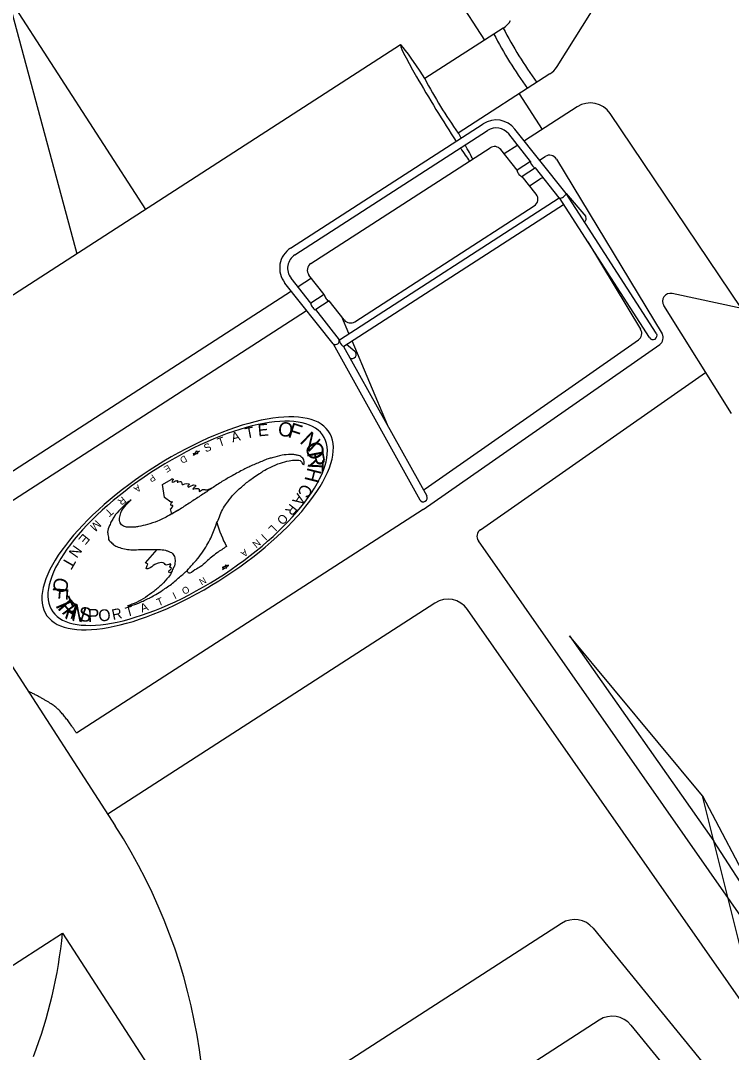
# Model space of a CAD drawing. Extents: x 2160312 to 2162215, y 789569 to 792090.
# Drawn here: x 2160629.46 to 2160646.64, y 791265.83 to 791290.78 of the extents above; entities that cross this region are included whole.
import ezdxf

# ---------------------------------------------------------------- set-up
doc = ezdxf.new("R2010")
doc.units = 0
doc.layers.add('DEV TITLE SHEET CELL', color=7, linetype='Continuous')

msp = doc.modelspace()

# ---------------------------------------------------------------- linework, layer by layer
at = {"layer": 'DEV TITLE SHEET CELL'}
for p, q in [((2160627.197, 791294.398), (2160632.481, 791286.212)), ((2160642.426, 791289.665), (2160645.071, 791293.874)), ((2160639.606, 791291.955), (2160640.671, 791290.305)), ((2160629.138, 791291.39), (2160630.822, 791285.141)), ((2160641.125, 791290.598), (2160639.229, 791289.374)), ((2160638.641, 791290.189), (2160626.105, 791282.097)), ((2160642.249, 791289.487), (2160640.038, 791288.059)), ((2160641.508, 791289.008), (2160642.066, 791288.145)), ((2160642.913, 791288.692), (2160641.637, 791287.868)), ((2160646.884, 791283.816), (2160643.707, 791288.529)), ((2160635.986, 791285.278), (2160640.641, 791288.283)), ((2160642.643, 791286.6), (2160641.408, 791288.156)), ((2160636.091, 791285.116), (2160640.745, 791288.121)), ((2160641.785, 791287.37), (2160641.257, 791288.036)), ((2160636.478, 791284.907), (2160640.807, 791287.702)), ((2160641.459, 791287.16), (2160641.063, 791287.659)), ((2160641.474, 791287.763), (2160641.148, 791287.553)), ((2160642.004, 791287.405), (2160642.142, 791287.493)), ((2160642.412, 791287.431), (2160644.963, 791283.203)), ((2160641.783, 791287.369), (2160641.459, 791287.16)), ((2160641.903, 791287.216), (2160641.58, 791287.008)), ((2160642.48, 791286.495), (2160641.905, 791287.219)), ((2160641.921, 791286.578), (2160641.58, 791287.008)), ((2160641.757, 791286.785), (2160642.017, 791286.953)), ((2160637.164, 791283.063), (2160642.48, 791286.495)), ((2160644.662, 791283.116), (2160642.481, 791286.495)), ((2160644.824, 791283.221), (2160642.643, 791286.6)), ((2160642.643, 791286.6), (2160643.119, 791286.037)), ((2160637.271, 791282.902), (2160642.585, 791286.333)), ((2160637.538, 791283.497), (2160641.875, 791286.296)), ((2160643.171, 791285.426), (2160644.446, 791283.313)), ((2160637.011, 791282.964), (2160635.847, 791284.432)), ((2160636.475, 791283.943), (2160635.998, 791284.552)), ((2160636.492, 791284.547), (2160636.166, 791284.337)), ((2160636.801, 791284.153), (2160636.43, 791284.625)), ((2160636.005, 791284.233), (2160626.216, 791277.914)), ((2160646.889, 791283.82), (2160645.208, 791284.177)), ((2160636.801, 791284.153), (2160636.475, 791283.943)), ((2160636.92, 791284), (2160636.595, 791283.79)), ((2160637.281, 791283.54), (2160636.92, 791284)), ((2160627.632, 791278.127), (2160636.373, 791283.769)), ((2160637.164, 791283.063), (2160636.595, 791283.79)), ((2160646.638, 791281.28), (2160645.005, 791283.886)), ((2160637.394, 791283.211), (2160637.224, 791283.613)), ((2160637.011, 791282.964), (2160639.108, 791279.192)), ((2160637.538, 791282.779), (2160637.336, 791282.946)), ((2160638.327, 791281.004), (2160637.47, 791283.031)), ((2160639.193, 791278.956), (2160644.908, 791282.946)), ((2160639.235, 791279.456), (2160644.391, 791283.055)), ((2160637.267, 791282.901), (2160639.276, 791279.286)), ((2160640.573, 791278.469), (2160646.017, 791282.27)), ((2160633.627, 791280.304), (2160633.688, 791280.329)), ((2160633.627, 791280.304), (2160633.688, 791280.329)), ((2160633.669, 791280.304), (2160633.627, 791280.304)), ((2160633.669, 791280.304), (2160633.627, 791280.304)), ((2160633.638, 791280.26), (2160633.669, 791280.304)), ((2160633.638, 791280.26), (2160633.669, 791280.304)), ((2160633.694, 791280.302), (2160633.638, 791280.26)), ((2160633.694, 791280.302), (2160633.638, 791280.26)), ((2160633.688, 791280.329), (2160633.718, 791280.373)), ((2160633.688, 791280.329), (2160633.718, 791280.373)), ((2160633.736, 791280.3), (2160633.694, 791280.302)), ((2160633.736, 791280.3), (2160633.694, 791280.302)), ((2160633.718, 791280.373), (2160633.725, 791280.345)), ((2160633.718, 791280.373), (2160633.725, 791280.345)), ((2160633.725, 791280.345), (2160633.783, 791280.369)), ((2160633.725, 791280.345), (2160633.783, 791280.369)), ((2160633.783, 791280.369), (2160633.73, 791280.327)), ((2160633.783, 791280.369), (2160633.73, 791280.327)), ((2160633.73, 791280.327), (2160633.736, 791280.3)), ((2160633.73, 791280.327), (2160633.736, 791280.3)), ((2160636.313, 791280.047), (2160636.305, 791280.046)), ((2160636.313, 791280.047), (2160636.305, 791280.046)), ((2160636.313, 791280.047), (2160636.305, 791280.046)), ((2160632.888, 791279.564), (2160633.1, 791279.682)), ((2160632.888, 791279.564), (2160633.1, 791279.682)), ((2160632.939, 791279.245), (2160632.888, 791279.564)), ((2160632.939, 791279.245), (2160632.888, 791279.564)), ((2160633.094, 791279.135), (2160632.939, 791279.245)), ((2160633.094, 791279.135), (2160632.939, 791279.245)), ((2160639.193, 791278.956), (2160630.814, 791273.547)), ((2160633.112, 791278.847), (2160633.084, 791278.976)), ((2160633.112, 791278.847), (2160633.084, 791278.976)), ((2160634.205, 791278.639), (2160634.205, 791278.639)), ((2160634.205, 791278.639), (2160634.205, 791278.639)), ((2160648.429, 791266.88), (2160640.525, 791278.2)), ((2160632.475, 791277.671), (2160632.76, 791277.988)), ((2160632.475, 791277.671), (2160632.76, 791277.988)), ((2160632.76, 791277.988), (2160632.76, 791277.988)), ((2160632.76, 791277.988), (2160632.76, 791277.988)), ((2160634.393, 791277.576), (2160634.333, 791277.551)), ((2160634.393, 791277.576), (2160634.333, 791277.551)), ((2160634.333, 791277.551), (2160634.373, 791277.55)), ((2160634.333, 791277.551), (2160634.373, 791277.55)), ((2160634.373, 791277.55), (2160634.343, 791277.507)), ((2160634.373, 791277.55), (2160634.343, 791277.507)), ((2160634.343, 791277.507), (2160634.399, 791277.549)), ((2160634.343, 791277.507), (2160634.399, 791277.549)), ((2160634.422, 791277.619), (2160634.393, 791277.576)), ((2160634.422, 791277.619), (2160634.393, 791277.576)), ((2160634.399, 791277.549), (2160634.442, 791277.548)), ((2160634.399, 791277.549), (2160634.442, 791277.548)), ((2160634.429, 791277.592), (2160634.422, 791277.619)), ((2160634.429, 791277.592), (2160634.422, 791277.619)), ((2160634.487, 791277.615), (2160634.429, 791277.592)), ((2160634.487, 791277.615), (2160634.429, 791277.592)), ((2160634.434, 791277.574), (2160634.487, 791277.615)), ((2160634.434, 791277.574), (2160634.487, 791277.615)), ((2160634.442, 791277.548), (2160634.434, 791277.574)), ((2160634.442, 791277.548), (2160634.434, 791277.574)), ((2160633.895, 791277.019), (2160633.895, 791277.019)), ((2160633.895, 791277.019), (2160633.895, 791277.019)), ((2160639.475, 791276.695), (2160631.565, 791271.589)), ((2160648.626, 791264.563), (2160640.264, 791276.54)), ((2160645.942, 791272.037), (2160642.724, 791275.906)), ((2160642.724, 791275.906), (2160646.217, 791270.935)), ((2160629.174, 791275.293), (2160631.748, 791271.306)), ((2160645.942, 791272.037), (2160647.839, 791268.415)), ((2160646.854, 791268.391), (2160645.942, 791272.037)), ((2160647.839, 791268.415), (2160646.217, 791270.935)), ((2160642.535, 791268.951), (2160633.917, 791263.388)), ((2160626.634, 791266.238), (2160630.476, 791268.718)), ((2160630.476, 791268.718), (2160633.917, 791263.388)), ((2160643.297, 791268.831), (2160650.056, 791260.549)), ((2160643.446, 791266.614), (2160633.389, 791260.122))]:
    msp.add_line(p, q, dxfattribs=at)
msp.add_lwpolyline([(2160644.208, 791266.493), (2160650.828, 791258.381), (2160655.726, 791248.545)], dxfattribs=at)
for centre, radius, start, end in [((2160640.811, 791291.084), 0.579, 302.8433, 327.8433), ((2160650.001, 791295.144), 10.24, 207.2706, 215.9184), ((2160650.226, 791295.29), 10.24, 207.2706, 215.9184), ((2160641.936, 791289.973), 0.579, 302.8433, 327.8433), ((2160648.33, 791294.066), 10.24, 207.2706, 215.9184), ((2160643.227, 791288.206), 0.579, 33.9826, 122.8433), ((2160640.954, 791287.796), 0.579, 38.4237, 122.8433), ((2160640.954, 791287.796), 0.386, 38.4237, 122.8433), ((2160640.912, 791287.539), 0.193, 38.4237, 122.8433), ((2160642.246, 791287.331), 0.193, 31.1078, 122.8433), ((2160642.122, 791286.791), 0.193, 98.4709, 122.8433), ((2160641.77, 791286.458), 0.193, 302.8433, 38.4237), ((2160643.035, 791285.989), 0.0965, 304.5431, 29.5006), ((2160636.3, 791284.792), 0.579, 122.8433, 218.4237), ((2160636.3, 791284.792), 0.386, 122.8433, 218.4237), ((2160636.582, 791284.744), 0.193, 122.8433, 218.0835), ((2160645.168, 791283.988), 0.193, 78.0134, 212.0784), ((2160637.433, 791283.659), 0.193, 218.0835, 302.8433), ((2160644.28, 791283.214), 0.193, 304.9228, 31.1078), ((2160644.746, 791283.163), 0.0965, 209.0651, 29.0651), ((2160644.797, 791283.104), 0.193, 304.9228, 31.1078), ((2160637.07, 791283.036), 0.0926, 209.4294, 50.8189), ((2160637.476, 791282.705), 0.0965, 234.6212, 50.4547), ((2160639.125, 791279.614), 0.193, 291.5281, 304.9228), ((2160639.192, 791279.239), 0.0965, 209.0651, 29.0651), ((2160640.683, 791278.311), 0.193, 124.9228, 214.9228), ((2160639.789, 791276.209), 0.579, 34.9228, 122.8433), ((2160620.295, 791263.912), 13.632, 343.8569, 32.8433), ((2160642.849, 791268.465), 0.579, 39.2178, 122.8433), ((2160618.976, 791269.857), 11.556, 339.0716, 354.3432), ((2160643.76, 791266.127), 0.579, 39.2178, 122.8433)]:
    msp.add_arc(centre, radius, start, end, dxfattribs=at)
for centre, major_axis, ratio, start_param, end_param in [((2160639.582, 791288.656), (-0.941, 1.533), 0.046583, 5.1713, 8.375165), ((2160639.582, 791288.656), (-0.941, 1.533), 0.046583, 4.195477, 4.283977), ((2160639.582, 791288.656), (-0.941, 1.533), 0.046583, 2.213476, 2.527889), ((2160639.582, 791288.656), (-0.941, 1.533), 0.046583, 3.752909, 4.070851), ((2160641.518, 791287.083), (0.0575, -0.0789), 0.259529, 3.225171, 6.472122), ((2160641.842, 791287.291), (0.0575, -0.0789), 0.259529, 3.225171, 6.472122), ((2160642.562, 791286.546), (0.081, 0.0538), 0.351139, 3.062724, 6.283185), ((2160636.535, 791283.865), (0.0575, -0.0789), 0.259529, 3.225171, 6.472122), ((2160636.86, 791284.075), (0.0575, -0.0789), 0.259529, 3.225171, 6.472122), ((2160637.217, 791282.983), (-0.0523, 0.0792), 0.293196, 6.282737, 9.424275), ((2160633.497, 791278.623), (3.418, 2.207), 0.387649, 4.580113, 7.721705), ((2160633.497, 791278.623), (3.418, 2.207), 0.387649, 4.580113, 7.721705), ((2160633.497, 791278.623), (3.276, 2.115), 0.387649, 4.580113, 7.721705), ((2160633.497, 791278.623), (3.276, 2.115), 0.387649, 4.580113, 7.721705), ((2160633.497, 791278.623), (-3.418, -2.207), 0.387649, 4.580113, 7.721705), ((2160633.497, 791278.623), (-3.418, -2.207), 0.387649, 4.580113, 7.721705), ((2160633.497, 791278.623), (-3.276, -2.115), 0.387649, 4.580113, 7.721705), ((2160633.497, 791278.623), (-3.276, -2.115), 0.387649, 4.580113, 7.721705), ((2160652.622, 791289.414), (-18.024, -11.635), 0.387649, 6.075485, 6.077223), ((2160652.622, 791289.414), (-18.024, -11.635), 0.387649, 6.075485, 6.077223), ((2160652.622, 791289.414), (-18.024, -11.635), 0.387649, 6.170414, 6.243823), ((2160652.622, 791289.414), (-18.024, -11.635), 0.387649, 6.170414, 6.243823)]:
    msp.add_ellipse(centre, major_axis=major_axis, ratio=ratio, start_param=start_param, end_param=end_param, dxfattribs=at)
for points in [[(2160636.305, 791280.046), (2160636.317, 791280.094), (2160636.281, 791280.195), (2160636.179, 791280.26), (2160636.165, 791280.263), (2160636.089, 791280.281), (2160635.982, 791280.285), (2160635.781, 791280.269), (2160635.543, 791280.208), (2160635.442, 791280.181), (2160635.321, 791280.133), (2160635.065, 791280.027), (2160634.822, 791279.908), (2160634.541, 791279.755), (2160634.297, 791279.612), (2160634.051, 791279.45), (2160633.804, 791279.285), (2160633.563, 791279.128), (2160633.315, 791278.967), (2160633.065, 791278.823), (2160633.043, 791278.811), (2160632.771, 791278.678), (2160632.525, 791278.593), (2160632.313, 791278.544), (2160632.214, 791278.53), (2160632.109, 791278.531), (2160632.049, 791278.531), (2160631.95, 791278.557), (2160631.866, 791278.635), (2160631.853, 791278.75), (2160631.883, 791278.876), (2160631.979, 791279.027), (2160632.131, 791279.19)], [(2160636.305, 791280.046), (2160636.317, 791280.094), (2160636.281, 791280.195), (2160636.179, 791280.26), (2160636.165, 791280.263), (2160636.089, 791280.281), (2160635.982, 791280.285), (2160635.781, 791280.269), (2160635.543, 791280.208), (2160635.442, 791280.181), (2160635.321, 791280.133), (2160635.065, 791280.027), (2160634.822, 791279.908), (2160634.541, 791279.755), (2160634.297, 791279.612), (2160634.051, 791279.45), (2160633.804, 791279.285), (2160633.563, 791279.128), (2160633.315, 791278.967), (2160633.065, 791278.823), (2160633.043, 791278.811), (2160632.771, 791278.678), (2160632.525, 791278.593), (2160632.313, 791278.544), (2160632.214, 791278.53), (2160632.109, 791278.531), (2160632.049, 791278.531), (2160631.95, 791278.557), (2160631.866, 791278.635), (2160631.853, 791278.75), (2160631.883, 791278.876), (2160631.979, 791279.027), (2160632.131, 791279.19)], [(2160632.044, 791276.626), (2160632.106, 791276.633), (2160632.325, 791276.702), (2160632.574, 791276.817), (2160632.598, 791276.829), (2160632.732, 791276.905), (2160632.887, 791277.003), (2160633.134, 791277.176), (2160633.355, 791277.367), (2160633.448, 791277.447), (2160633.535, 791277.539), (2160633.705, 791277.728), (2160633.839, 791277.902), (2160633.964, 791278.097), (2160634.057, 791278.263), (2160634.123, 791278.425), (2160634.183, 791278.585), (2160634.248, 791278.741), (2160634.318, 791278.907), (2160634.417, 791279.077), (2160634.429, 791279.092), (2160634.577, 791279.289), (2160634.771, 791279.477), (2160634.976, 791279.648), (2160635.088, 791279.73), (2160635.234, 791279.825), (2160635.317, 791279.881), (2160635.495, 791279.976), (2160635.741, 791280.081), (2160635.949, 791280.134), (2160636.119, 791280.153), (2160636.24, 791280.121), (2160636.305, 791280.046), (2160636.313, 791280.047)], [(2160632.044, 791276.626), (2160632.106, 791276.633), (2160632.325, 791276.702), (2160632.574, 791276.817), (2160632.598, 791276.829), (2160632.732, 791276.905), (2160632.887, 791277.003), (2160633.134, 791277.176), (2160633.355, 791277.367), (2160633.448, 791277.447), (2160633.535, 791277.539), (2160633.705, 791277.728), (2160633.839, 791277.902), (2160633.964, 791278.097), (2160634.057, 791278.263), (2160634.123, 791278.425), (2160634.183, 791278.585), (2160634.248, 791278.741), (2160634.318, 791278.907), (2160634.417, 791279.077), (2160634.429, 791279.092), (2160634.577, 791279.289), (2160634.771, 791279.477), (2160634.976, 791279.648), (2160635.088, 791279.73), (2160635.234, 791279.825), (2160635.317, 791279.881), (2160635.495, 791279.976), (2160635.741, 791280.081), (2160635.949, 791280.134), (2160636.119, 791280.153), (2160636.24, 791280.121), (2160636.305, 791280.046), (2160636.313, 791280.047)], [(2160633.1, 791279.682), (2160633.119, 791279.697), (2160633.146, 791279.693), (2160633.116, 791279.625), (2160633.164, 791279.627), (2160633.207, 791279.652), (2160633.254, 791279.658), (2160633.248, 791279.62), (2160633.333, 791279.636), (2160633.353, 791279.619), (2160633.366, 791279.564), (2160633.523, 791279.581), (2160633.538, 791279.559), (2160633.502, 791279.531), (2160633.499, 791279.51), (2160633.622, 791279.549), (2160633.641, 791279.552), (2160633.697, 791279.526), (2160633.679, 791279.501), (2160633.628, 791279.467), (2160633.62, 791279.454), (2160633.65, 791279.453), (2160633.718, 791279.466), (2160633.774, 791279.451), (2160633.774, 791279.397), (2160633.86, 791279.437), (2160633.954, 791279.429), (2160634.006, 791279.445), (2160634.056, 791279.471)], [(2160633.1, 791279.682), (2160633.119, 791279.697), (2160633.146, 791279.693), (2160633.116, 791279.625), (2160633.164, 791279.627), (2160633.207, 791279.652), (2160633.254, 791279.658), (2160633.248, 791279.62), (2160633.333, 791279.636), (2160633.353, 791279.619), (2160633.366, 791279.564), (2160633.523, 791279.581), (2160633.538, 791279.559), (2160633.502, 791279.531), (2160633.499, 791279.51), (2160633.622, 791279.549), (2160633.641, 791279.552), (2160633.697, 791279.526), (2160633.679, 791279.501), (2160633.628, 791279.467), (2160633.62, 791279.454), (2160633.65, 791279.453), (2160633.718, 791279.466), (2160633.774, 791279.451), (2160633.774, 791279.397), (2160633.86, 791279.437), (2160633.954, 791279.429), (2160634.006, 791279.445), (2160634.056, 791279.471)], [(2160634.057, 791279.454), (2160634.051, 791279.45), (2160633.804, 791279.285), (2160633.563, 791279.128), (2160633.315, 791278.967), (2160633.112, 791278.848)], [(2160634.057, 791279.454), (2160634.051, 791279.45), (2160633.804, 791279.285), (2160633.563, 791279.128), (2160633.315, 791278.967), (2160633.112, 791278.848)], [(2160632.131, 791279.19), (2160632.055, 791279.133), (2160631.872, 791278.963), (2160631.724, 791278.783), (2160631.716, 791278.768), (2160631.656, 791278.672), (2160631.612, 791278.572), (2160631.563, 791278.413), (2160631.581, 791278.286), (2160631.588, 791278.232), (2160631.625, 791278.187), (2160631.709, 791278.106), (2160631.817, 791278.049), (2160631.973, 791278.007), (2160632.122, 791277.985), (2160632.306, 791277.986), (2160632.493, 791277.991), (2160632.668, 791277.989), (2160632.845, 791277.986), (2160632.997, 791277.96), (2160633.009, 791277.955), (2160633.133, 791277.894), (2160633.185, 791277.791), (2160633.191, 791277.67), (2160633.179, 791277.599), (2160633.135, 791277.504), (2160633.117, 791277.449), (2160633.035, 791277.325), (2160632.874, 791277.145), (2160632.678, 791276.978), (2160632.476, 791276.831), (2160632.258, 791276.711), (2160632.044, 791276.626)], [(2160632.131, 791279.19), (2160632.055, 791279.133), (2160631.872, 791278.963), (2160631.724, 791278.783), (2160631.716, 791278.768), (2160631.656, 791278.672), (2160631.612, 791278.572), (2160631.563, 791278.413), (2160631.581, 791278.286), (2160631.588, 791278.232), (2160631.625, 791278.187), (2160631.709, 791278.106), (2160631.817, 791278.049), (2160631.973, 791278.007), (2160632.122, 791277.985), (2160632.306, 791277.986), (2160632.493, 791277.991), (2160632.668, 791277.989), (2160632.845, 791277.986), (2160632.997, 791277.96), (2160633.009, 791277.955), (2160633.133, 791277.894), (2160633.185, 791277.791), (2160633.191, 791277.67), (2160633.179, 791277.599), (2160633.135, 791277.504), (2160633.117, 791277.449), (2160633.035, 791277.325), (2160632.874, 791277.145), (2160632.678, 791276.978), (2160632.476, 791276.831), (2160632.258, 791276.711), (2160632.044, 791276.626)], [(2160633.084, 791278.976), (2160633.131, 791279.018), (2160633.141, 791279.051), (2160633.094, 791279.063), (2160633.091, 791279.09), (2160633.128, 791279.142), (2160633.094, 791279.135)], [(2160633.084, 791278.976), (2160633.131, 791279.018), (2160633.141, 791279.051), (2160633.094, 791279.063), (2160633.091, 791279.09), (2160633.128, 791279.142), (2160633.094, 791279.135)], [(2160633.482, 791277.48), (2160633.535, 791277.539), (2160633.705, 791277.728), (2160633.839, 791277.902), (2160633.964, 791278.097), (2160634.057, 791278.263), (2160634.123, 791278.425), (2160634.183, 791278.585), (2160634.205, 791278.639)], [(2160633.482, 791277.48), (2160633.535, 791277.539), (2160633.705, 791277.728), (2160633.839, 791277.902), (2160633.964, 791278.097), (2160634.057, 791278.263), (2160634.123, 791278.425), (2160634.183, 791278.585), (2160634.205, 791278.639)], [(2160632.76, 791277.988), (2160632.845, 791277.986), (2160632.997, 791277.96), (2160633.009, 791277.955), (2160633.133, 791277.894), (2160633.185, 791277.791), (2160633.191, 791277.67), (2160633.179, 791277.599), (2160633.135, 791277.504), (2160633.117, 791277.452)], [(2160632.76, 791277.988), (2160632.845, 791277.986), (2160632.997, 791277.96), (2160633.009, 791277.955), (2160633.133, 791277.894), (2160633.185, 791277.791), (2160633.191, 791277.67), (2160633.179, 791277.599), (2160633.135, 791277.504), (2160633.117, 791277.452)], [(2160634.435, 791278.063), (2160634.207, 791277.906), (2160633.946, 791277.692), (2160633.804, 791277.569), (2160633.674, 791277.496), (2160633.516, 791277.42), (2160633.484, 791277.48)], [(2160634.435, 791278.063), (2160634.207, 791277.906), (2160633.946, 791277.692), (2160633.804, 791277.569), (2160633.674, 791277.496), (2160633.516, 791277.42), (2160633.484, 791277.48)], [(2160633.116, 791277.452), (2160633.051, 791277.432), (2160633.041, 791277.454), (2160633.104, 791277.538), (2160633.068, 791277.577), (2160633.092, 791277.618), (2160633.09, 791277.634), (2160632.978, 791277.613), (2160632.94, 791277.65), (2160632.786, 791277.656), (2160632.703, 791277.629), (2160632.537, 791277.526), (2160632.499, 791277.527), (2160632.501, 791277.557), (2160632.532, 791277.633), (2160632.475, 791277.671)], [(2160633.116, 791277.452), (2160633.051, 791277.432), (2160633.041, 791277.454), (2160633.104, 791277.538), (2160633.068, 791277.577), (2160633.092, 791277.618), (2160633.09, 791277.634), (2160632.978, 791277.613), (2160632.94, 791277.65), (2160632.786, 791277.656), (2160632.703, 791277.629), (2160632.537, 791277.526), (2160632.499, 791277.527), (2160632.501, 791277.557), (2160632.532, 791277.633), (2160632.475, 791277.671)]]:
    msp.add_spline(points, degree=3, dxfattribs=at)
msp.add_open_spline([(2160630.814, 791273.547), (2160630.555, 791273.949), (2160630.167, 791274.313), (2160629.664, 791274.553)], degree=2, dxfattribs=at)
msp.add_open_spline([(2160630.814, 791273.547), (2160630.555, 791273.949), (2160630.167, 791274.313), (2160629.664, 791274.553)], degree=2, dxfattribs=at)

# ---------------------------------------------------------------- texts
for s, height, rotation, p in [('T', 0.26, 10.7589, (2160634.915, 791280.669)), ('E', 0.291, 5.2613, (2160635.205, 791280.723)), ('O', 0.345, 352.6392, (2160635.666, 791280.745)), ('F', 0.373, 341.953, (2160635.897, 791280.713)), ('T', 0.21, 19.1255, (2160634.261, 791280.469)), ('A', 0.234, 15.2685, (2160634.586, 791280.579)), ('N', 0.402, 316.5595, (2160636.188, 791280.586)), ('S', 0.191, 22.2189, (2160633.934, 791280.336)), ('O', 0.406, 297.4571, (2160636.301, 791280.476)), ('D', 0.162, 209.0421, (2160633.428, 791280.273)), ('R', 0.397, 281.2949, (2160636.378, 791280.328)), ('E', 0.157, 211.5092, (2160633.026, 791280.048)), ('H', 0.353, 256.0342, (2160636.399, 791279.988)), ('T', 0.38, 267.5346, (2160636.409, 791280.171)), ('P', 0.158, 214.4328, (2160632.652, 791279.815)), ('A', 0.163, 217.0274, (2160632.295, 791279.57)), ('C', 0.299, 242.0124, (2160636.274, 791279.601)), ('R', 0.173, 219.9192, (2160631.919, 791279.284)), ('A', 0.267, 235.9351, (2160636.148, 791279.367)), ('T', 0.187, 222.8194, (2160631.592, 791279.008)), ('R', 0.241, 231.6865, (2160635.978, 791279.115)), ('M', 0.207, 226.2777, (2160631.283, 791278.718)), ('O', 0.216, 227.6233, (2160635.787, 791278.874)), ('L', 0.196, 224.4927, (2160635.538, 791278.601)), ('E', 0.232, 230.3342, (2160630.976, 791278.392)), ('N', 0.174, 220.1559, (2160635.172, 791278.255)), ('I', 0.187, 222.6432, (2160635.308, 791278.379)), ('N', 0.26, 234.77, (2160630.752, 791278.118)), ('A', 0.163, 217.1063, (2160634.879, 791278.01)), ('T', 0.289, 239.9995, (2160630.558, 791277.839)), ('O', 0.348, 254.19, (2160630.311, 791277.346)), ('N', 0.159, 30.7562, (2160633.837, 791277.118)), ('F', 0.375, 265.2651, (2160630.245, 791277.095)), ('I', 0.174, 25.768, (2160633.188, 791276.782)), ('O', 0.165, 27.8835, (2160633.413, 791276.892)), ('T', 0.403, 293.3717, (2160630.26, 791276.731)), ('R', 0.405, 311.1929, (2160630.335, 791276.568)), ('A', 0.393, 327.3231, (2160630.456, 791276.44)), ('A', 0.204, 19.9864, (2160632.395, 791276.464)), ('T', 0.185, 23.3187, (2160632.796, 791276.612)), ('N', 0.372, 341.1768, (2160630.631, 791276.335)), ('S', 0.344, 352.1317, (2160630.843, 791276.271)), ('P', 0.314, 0.469, (2160631.085, 791276.239)), ('O', 0.285, 6.5651, (2160631.356, 791276.243)), ('R', 0.255, 11.8724, (2160631.693, 791276.284)), ('T', 0.23, 15.6624, (2160632.03, 791276.358))]:
    msp.add_text(s, height=height, rotation=rotation, dxfattribs=at).set_placement(p)

doc.saveas('drawing.dxf')
